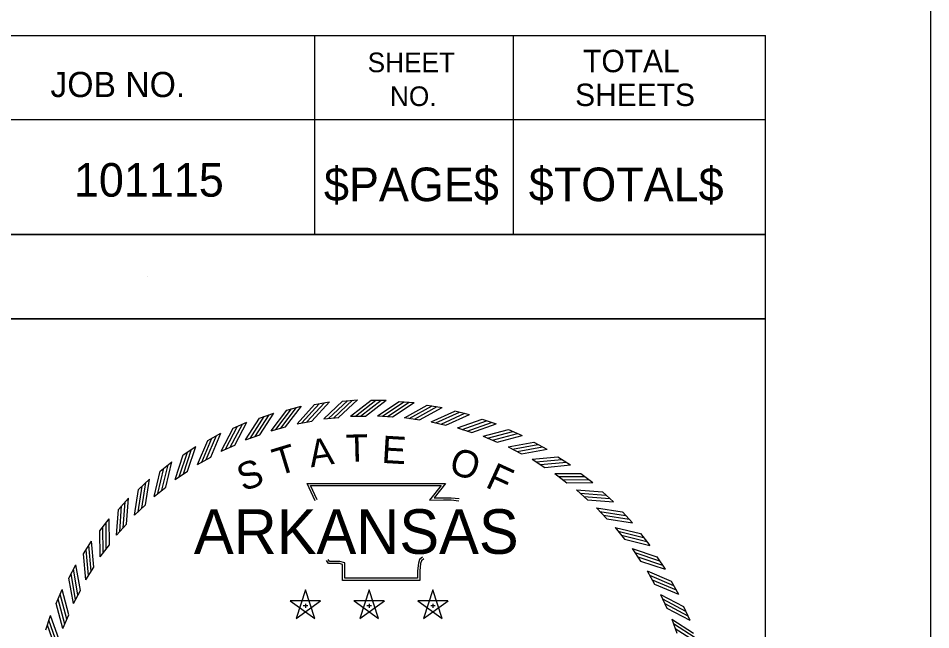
# Model space of a CAD drawing. Extents: x 0 to 1228740, y 0 to 152440.
# Drawn here: x 30.816 to 34, y 19.35 to 21.483 of the extents above; entities that cross this region are included whole.
import ezdxf

# ---------------------------------------------------------------- set-up
doc = ezdxf.new("R2010")
doc.units = 0
for name, color, linetype in [('R_Border', 7, 'Continuous'), ('R_No Plot', 7, 'Continuous'), ('STAMP_PP', 7, 'Continuous')]:
    doc.layers.add(name, color=color, linetype=linetype)

msp = doc.modelspace()

# ---------------------------------------------------------------- linework, layer by layer
at = {"layer": 'R_Border'}
for p, q in [((1.516, 21.4232), (33.4231, 21.4232)), ((31.8491, 21.4232), (31.8491, 20.7292)), ((32.5431, 21.4232), (32.5431, 20.7292)), ((33.4231, 0.5768), (33.4231, 21.4232)), ((33.4231, 21.1292), (29.1131, 21.1292)), ((33.4231, 21.1312), (33.4231, 21.1312)), ((33.4231, 20.7292), (29.1131, 20.7292)), ((29.4091, 20.7292), (33.4231, 20.7292)), ((33.4231, 20.4352), (27.1591, 20.4352))]:
    msp.add_line(p, q, dxfattribs=at)
msp.add_lwpolyline([(33.9999, 22), (0, 22), (0, 0), (33.9999, 0)], close=True, dxfattribs=at)
at = {"layer": 'R_No Plot'}
for p, q in [((31.2681, 20.5822), (31.2681, 20.5823)), ((29.1131, 20.4352), (33.4231, 20.4352))]:
    msp.add_line(p, q, dxfattribs=at)
msp.add_lwpolyline([(31.2681, 20.5822), (31.2681, 20.5822), (31.2681, 20.5822)], dxfattribs=at)
at = {"layer": 'STAMP_PP'}
for p, q in [((31.7528, 20.1161), (31.8035, 20.1294)), ((31.8496, 20.1358), (31.9012, 20.1449)), ((31.9477, 20.1476), (31.9999, 20.1524)), ((32.0469, 20.1505), (32.0993, 20.1505)), ((32.1451, 20.1465), (32.1973, 20.1427)), ((32.243, 20.1338), (32.2948, 20.1257)), ((31.658, 20.0884), (31.7074, 20.1058)), ((31.9754, 20.0947), (32.0279, 20.0947)), ((32.0697, 20.0962), (32.1221, 20.0923)), ((32.3396, 20.1131), (32.3905, 20.1007)), ((31.5658, 20.0529), (31.6136, 20.0744)), ((31.7889, 20.0685), (31.8406, 20.0776)), ((31.8816, 20.0855), (31.9339, 20.0903)), ((32.1637, 20.0899), (32.2156, 20.0817)), ((32.2569, 20.0758), (32.308, 20.0634)), ((32.4341, 20.0844), (32.4839, 20.0678)), ((31.4769, 20.01), (31.5227, 20.0354)), ((31.6092, 20.0119), (31.6587, 20.0295)), ((31.6979, 20.0439), (31.7487, 20.0573)), ((32.3487, 20.0541), (32.3985, 20.0375)), ((32.526, 20.048), (32.5742, 20.0274)), ((32.4383, 20.0249), (32.4866, 20.0042)), ((32.6145, 20.0042), (32.6608, 19.9797)), ((31.3917, 19.9599), (31.4354, 19.9889)), ((31.5235, 19.9727), (31.5714, 19.9943)), ((32.5252, 19.9884), (32.5716, 19.9638)), ((31.3111, 19.9029), (31.3521, 19.9354)), ((31.4413, 19.9266), (31.4872, 19.952)), ((32.6088, 19.9448), (32.653, 19.9165)), ((32.6991, 19.9532), (32.7432, 19.9249)), ((31.3632, 19.8738), (31.4069, 19.9029)), ((31.2354, 19.8394), (31.2736, 19.8753)), ((32.6885, 19.8945), (32.7303, 19.8626)), ((32.7792, 19.8954), (32.8208, 19.8636)), ((31.2897, 19.8147), (31.3308, 19.8474)), ((32.7638, 19.8377), (32.8028, 19.8025)), ((31.1652, 19.7699), (31.2003, 19.8088)), ((32.8542, 19.8312), (32.8931, 19.796)), ((31.2213, 19.7498), (31.2597, 19.7858)), ((32.8341, 19.775), (32.8701, 19.7367)), ((32.9237, 19.761), (32.9596, 19.7227)), ((31.1009, 19.6949), (31.1327, 19.7365)), ((31.1586, 19.6795), (31.1938, 19.7185)), ((32.8991, 19.7066), (32.9317, 19.6655)), ((32.9872, 19.6853), (33.0198, 19.6442)), ((31.0431, 19.6148), (31.0714, 19.6589)), ((31.1019, 19.6042), (31.1337, 19.6459)), ((32.9581, 19.6331), (32.9872, 19.5894)), ((33.0442, 19.6046), (33.0732, 19.561)), ((30.9921, 19.5302), (31.0167, 19.5765)), ((31.0515, 19.5245), (31.0799, 19.5687)), ((33.0109, 19.555), (33.0363, 19.5091)), ((33.0943, 19.5195), (33.1197, 19.4736)), ((30.9483, 19.4417), (30.9689, 19.4898)), ((31.8179, 19.4893), (31.7852, 19.3887)), ((31.8506, 19.3888), (31.818, 19.4894)), ((32.0402, 19.4893), (32.0074, 19.3887)), ((32.0729, 19.3888), (32.0403, 19.4894)), ((32.2625, 19.4893), (32.2297, 19.3887)), ((32.2952, 19.3888), (32.2626, 19.4894)), ((31.008, 19.4409), (31.0325, 19.4873)), ((33.0571, 19.4728), (33.0786, 19.4249)), ((31.8708, 19.4509), (31.765, 19.451)), ((31.7651, 19.4509), (31.8506, 19.3887)), ((31.7853, 19.3888), (31.8709, 19.4509)), ((31.8104, 19.434), (31.8261, 19.434)), ((31.818, 19.4397), (31.818, 19.4264)), ((32.0931, 19.4509), (31.9873, 19.451)), ((31.9874, 19.4509), (32.0729, 19.3887)), ((32.0076, 19.3888), (32.0932, 19.4509)), ((32.0327, 19.434), (32.0484, 19.434)), ((32.0403, 19.4397), (32.0403, 19.4264)), ((32.3153, 19.4509), (32.2096, 19.451)), ((32.2096, 19.4509), (32.2952, 19.3887)), ((32.2298, 19.3888), (32.3155, 19.4509)), ((32.255, 19.434), (32.2707, 19.434)), ((32.2626, 19.4397), (32.2626, 19.4264)), ((33.1372, 19.4305), (33.1587, 19.3827)), ((30.9119, 19.3498), (30.9285, 19.3995)), ((30.9714, 19.354), (30.9921, 19.4023)), ((33.0963, 19.3871), (33.1138, 19.3376))]:
    msp.add_line(p, q, dxfattribs=at)
for points in [[(31.7317, 20.053), (31.7866, 20.1252)], [(31.7486, 20.0573), (31.8036, 20.1294)], [(31.7888, 20.0684), (31.8496, 20.1358)], [(31.8055, 20.0712), (31.8662, 20.1386)], [(31.8233, 20.0748), (31.884, 20.1421)], [(31.8405, 20.0777), (31.9013, 20.145)], [(31.8816, 20.0854), (31.9476, 20.1475)], [(31.8984, 20.0868), (31.9644, 20.1489)], [(31.9165, 20.0889), (31.9825, 20.151)], [(31.9338, 20.0903), (31.9999, 20.1524)], [(31.9754, 20.0947), (32.0469, 20.1504)], [(31.9922, 20.0945), (32.0637, 20.1503)], [(32.0104, 20.0949), (32.0819, 20.1507)], [(32.0279, 20.0948), (32.0994, 20.1505)], [(32.0696, 20.0961), (32.145, 20.1465)], [(32.0864, 20.0947), (32.1618, 20.1451)], [(32.1046, 20.0938), (32.18, 20.1442)], [(32.122, 20.0924), (32.1974, 20.1427)], [(32.1637, 20.0898), (32.243, 20.1338)], [(32.1803, 20.0871), (32.2596, 20.131)], [(32.1983, 20.0846), (32.2776, 20.1286)], [(32.2156, 20.0817), (32.2949, 20.1257)], [(31.6251, 20.0174), (31.6739, 20.0938)], [(31.6421, 20.0238), (31.691, 20.1002)], [(31.6586, 20.0295), (31.7075, 20.1059)], [(31.6978, 20.0439), (31.7528, 20.116)], [(31.7142, 20.048), (31.7691, 20.1201)], [(32.2569, 20.0758), (32.3395, 20.113)], [(32.2732, 20.0716), (32.3559, 20.1089)], [(32.291, 20.0677), (32.3737, 20.105)], [(32.3079, 20.0634), (32.3906, 20.1007)], [(31.5553, 19.9873), (31.5977, 20.0675)], [(31.5713, 19.9943), (31.6136, 20.0745)], [(31.6092, 20.0119), (31.658, 20.0883)], [(32.3486, 20.0541), (32.4341, 20.0844)], [(32.3646, 20.0486), (32.45, 20.0789)], [(32.382, 20.0432), (32.4674, 20.0735)], [(32.3985, 20.0375), (32.4839, 20.0679)], [(31.4872, 19.952), (31.5227, 20.0354)], [(31.5234, 19.9727), (31.5658, 20.0528)], [(31.5389, 19.9794), (31.5812, 20.0596)], [(32.4382, 20.0249), (32.5259, 20.048)], [(32.4537, 20.0181), (32.5413, 20.0412)], [(32.4706, 20.0113), (32.5582, 20.0344)], [(31.4412, 19.9265), (31.4768, 20.0099)], [(31.4561, 19.9345), (31.4917, 20.0179)], [(31.4718, 19.9437), (31.5074, 20.0271)], [(32.4866, 20.0043), (32.5742, 20.0274)], [(32.5251, 19.9883), (32.6144, 20.0042)], [(31.3773, 19.883), (31.4058, 19.969)], [(31.3922, 19.8934), (31.4208, 19.9794)], [(31.4068, 19.9029), (31.4354, 19.989)], [(32.54, 19.9803), (32.6292, 19.9962)], [(32.5562, 19.9722), (32.6455, 19.988)], [(32.5716, 19.9638), (32.6609, 19.9797)], [(31.3308, 19.8474), (31.3521, 19.9355)], [(31.3631, 19.8737), (31.3917, 19.9598)], [(32.6087, 19.9448), (32.699, 19.9532)], [(32.6228, 19.9356), (32.7131, 19.944)], [(32.6384, 19.9261), (32.7287, 19.9345)], [(31.2897, 19.8147), (31.311, 19.9028)], [(31.303, 19.825), (31.3243, 19.9132)], [(31.317, 19.8367), (31.3384, 19.9248)], [(32.653, 19.9165), (32.7433, 19.9249)], [(31.2596, 19.7857), (31.2736, 19.8753)], [(32.6884, 19.8945), (32.7791, 19.8954)], [(32.7017, 19.8841), (32.7924, 19.885)], [(32.7165, 19.8734), (32.8071, 19.8743)], [(31.2213, 19.7498), (31.2353, 19.8393)], [(31.2337, 19.7612), (31.2478, 19.8508)], [(31.2467, 19.7739), (31.2608, 19.8635)], [(31.8517, 19.7998), (31.8238, 19.8602), (32.3071, 19.8605), (32.2667, 19.8098), (32.2995, 19.8102), (32.3269, 19.8106), (32.3543, 19.8076)], [(31.8586, 19.803), (31.8357, 19.8526), (32.2912, 19.8529), (32.2506, 19.8019), (32.2996, 19.8026), (32.3266, 19.8029), (32.3535, 19.8)], [(32.7302, 19.8627), (32.8209, 19.8636)], [(32.7637, 19.8377), (32.8542, 19.8312)], [(31.1937, 19.7184), (31.2003, 19.8089)], [(32.7761, 19.8263), (32.8666, 19.8198)], [(32.7899, 19.8144), (32.8803, 19.8078)], [(31.17, 19.6918), (31.1766, 19.7823)], [(31.1819, 19.7056), (31.1885, 19.796)], [(32.8027, 19.8026), (32.8932, 19.796)], [(32.8341, 19.775), (32.9236, 19.761)], [(31.1586, 19.6794), (31.1651, 19.7698)], [(32.8455, 19.7626), (32.9351, 19.7486)], [(32.8582, 19.7496), (32.9478, 19.7356)], [(31.1229, 19.6321), (31.122, 19.7228)], [(31.1337, 19.6459), (31.1327, 19.7366)], [(32.8701, 19.7367), (32.9596, 19.7227)], [(31.1019, 19.6041), (31.1009, 19.6948)], [(31.1122, 19.6174), (31.1113, 19.7081)], [(32.899, 19.7066), (32.9871, 19.6853)], [(32.9093, 19.6933), (32.9975, 19.672)], [(32.921, 19.6793), (33.0091, 19.658)], [(31.0798, 19.5687), (31.0714, 19.659)], [(32.9317, 19.6655), (33.0198, 19.6442)], [(31.0608, 19.5385), (31.0524, 19.6288)], [(31.0702, 19.5541), (31.0618, 19.6444)], [(32.958, 19.6332), (33.0441, 19.6046)], [(32.9673, 19.6191), (33.0533, 19.5905)], [(31.0515, 19.5244), (31.0431, 19.6147)], [(32.2309, 19.5972), (32.2227, 19.5905), (32.2199, 19.5805), (32.2172, 19.5554), (32.2172, 19.522), (31.9474, 19.522), (31.9474, 19.5671), (31.9474, 19.5772), (31.9365, 19.5805), (31.8981, 19.5805), (31.8913, 19.5909)], [(32.2261, 19.6032), (32.2159, 19.5949), (32.2124, 19.5819), (32.2095, 19.5559), (32.2095, 19.5297), (31.9551, 19.5297), (31.9551, 19.5671), (31.9551, 19.5828), (31.9376, 19.5882), (31.9022, 19.5882), (31.8977, 19.5951)], [(32.9777, 19.6041), (33.0637, 19.5756)], [(32.9872, 19.5895), (33.0733, 19.561)], [(31.0242, 19.4719), (31.0083, 19.5612)], [(31.0325, 19.4873), (31.0166, 19.5766)], [(33.0108, 19.5551), (33.0942, 19.5195)], [(31.008, 19.4408), (30.9921, 19.5301)], [(31.016, 19.4557), (31.0002, 19.5449)], [(33.0189, 19.5402), (33.1023, 19.5047)], [(33.028, 19.5245), (33.1114, 19.4889)], [(30.992, 19.4022), (30.9689, 19.4899)], [(33.0363, 19.5092), (33.1197, 19.4736)], [(30.9782, 19.3694), (30.9551, 19.457)], [(30.985, 19.3863), (30.9619, 19.4739)], [(33.057, 19.4729), (33.1372, 19.4305)], [(33.0638, 19.4574), (33.1439, 19.4151)], [(30.9715, 19.3539), (30.9483, 19.4416)], [(33.0716, 19.441), (33.1518, 19.3987)], [(33.0786, 19.425), (33.1588, 19.3827)], [(30.9588, 19.3142), (30.9285, 19.3996)], [(30.9477, 19.2802), (30.9174, 19.3657)], [(30.9531, 19.2976), (30.9228, 19.3831)], [(33.0962, 19.3872), (33.1726, 19.3384)], [(33.1017, 19.3712), (33.1781, 19.3224)], [(33.1081, 19.3542), (33.1845, 19.3054)]]:
    msp.add_lwpolyline(points, dxfattribs=at)

# ---------------------------------------------------------------- texts
at = {"layer": 'R_Border'}
for s, height, p in [('TOTAL', 0.07819, (32.7869, 21.2952)), ('SHEET', 0.0684, (32.0349, 21.2952)), ('JOB NO.', 0.08792, (30.9281, 21.2084)), ('NO.', 0.0684, (32.1129, 21.1772)), ('SHEETS', 0.07819, (32.7589, 21.1772)), ('101115', 0.11724, (31.0099, 20.8609)), ('$PAGE$', 0.11723, (31.8826, 20.8452)), ('$TOTAL$', 0.11723, (32.5975, 20.8452))]:
    msp.add_text(s, height=height, dxfattribs=at).set_placement(p)
at = {"layer": 'STAMP_PP'}
for s, rotation, p in [('T', 1.4789, (31.9601, 19.9351)), ('T', 16.9015, (31.7212, 19.8859)), ('A', 8.6788, (31.837, 19.9161)), ('E', 356.672, (32.0821, 19.9322)), ('O', 341.2218, (32.3136, 19.8995)), ('S', 19.7726, (31.6, 19.8315)), ('F', 335.3628, (32.442, 19.8492))]:
    msp.add_text(s, height=0.0953, rotation=rotation, dxfattribs=at).set_placement(p)
msp.add_text('ARKANSAS', height=0.15559, dxfattribs=at).set_placement((31.4287, 19.6146))

doc.saveas('drawing.dxf')
